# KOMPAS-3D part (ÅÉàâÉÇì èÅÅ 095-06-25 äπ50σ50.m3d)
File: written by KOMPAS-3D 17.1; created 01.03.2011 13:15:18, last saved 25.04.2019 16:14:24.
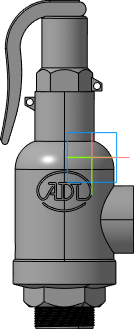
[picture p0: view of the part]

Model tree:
1. Операция без истории:2

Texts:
  Viktor2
